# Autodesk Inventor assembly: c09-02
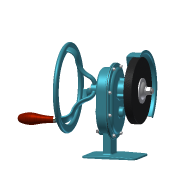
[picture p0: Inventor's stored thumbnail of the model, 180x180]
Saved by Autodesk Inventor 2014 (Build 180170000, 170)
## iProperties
Created: 2010-12
Part Number: c09-02
Document SubType Name: Assembly
Designer: Thom Tremblay
Author: Thom Tremblay
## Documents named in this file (27)
- C:\Inventor 2014 Essentials\Assemblies\Chapter 09\c09-02.iam
- C:\Inventor 2014 Essentials\Content Center Files\en-US\ANSI B93.98M\ANSI_B93.98M - 15x35x7-Type 2.ipt
- C:\Inventor 2014 Essentials\Content Center Files\en-US\SKF B - angular contact\SKF B7202 BE.ipt
- C:\Inventor 2014 Essentials\Content Center Files\en-US\IS 7483\IS 7483 - M4 x 8.ipt
- C:\Inventor 2014 Essentials\Content Center Files\en-US\ISO 2795  F\ISO 2795 - 10 x 14 x 10F.ipt
- C:\Inventor 2014 Essentials\Content Center Files\en-US\STN 022930\STN 022930 - 10.ipt
- C:\Inventor 2014 Essentials\Content Center Files\en-US\STN 022930\STN 022930 - 15.ipt
- C:\Inventor 2014 Essentials\Content Center Files\en-US\DIN 128\DIN 128 - A12.ipt
- C:\Inventor 2014 Essentials\Content Center Files\en-US\ISO 4032\ISO 4032 - M12ISO.ipt
- C:\Inventor 2014 Essentials\Content Center Files\en-US\ISO 4145 T8\ISO 4145 Plug T8 1_8.ipt
- C:\Inventor 2014 Essentials\Parts\Chapter 09\c09-01.ipt
- C:\Inventor 2014 Essentials\Parts\Chapter 09\c09-02.ipt
- C:\Inventor 2014 Essentials\Parts\Chapter 09\c09-03.ipt
- C:\Inventor 2014 Essentials\Parts\Chapter 09\c09-04.ipt
- C:\Inventor 2014 Essentials\Parts\Chapter 09\c09-05.ipt
- C:\Inventor 2014 Essentials\Parts\Chapter 09\c09-08.ipt
- C:\Inventor 2014 Essentials\Parts\Chapter 09\c09-06.ipt
- C:\Inventor 2014 Essentials\Parts\Chapter 09\c09-07.ipt
- C:\Inventor 2014 Essentials\Assemblies\Chapter 09\Design Accelerators\Shaft c09-01.iam
- C:\Inventor 2014 Essentials\Assemblies\Chapter 09\Design Accelerators\Shaft c09-02.iam
- C:\Inventor 2014 Essentials\Assemblies\Chapter 09\Design Accelerators\Shaft c09-03.iam
- C:\Inventor 2014 Essentials\Assemblies\Chapter 09\Design Accelerators\Cut Gear c09-01.iam
- C:\Inventor 2014 Essentials\Assemblies\Chapter 09\Design Accelerators\Cut Gear c09-02.iam
- C:\Inventor 2014 Essentials\Assemblies\Chapter 09\Design Accelerators\Spur Gear c09-01.iam
- C:\Inventor 2014 Essentials\Assemblies\Chapter 09\Design Accelerators\Key Connection c09-01.iam
- C:\Inventor 2014 Essentials\Assemblies\Chapter 09\Design Accelerators\Bolted Connection c09-01.iam
- C:\Inventor 2014 Essentials\Assemblies\Chapter 09\Design Accelerators\Bolted Connection c09-02.iam
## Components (31 placed, 24 different names)
1. c09-01:1 — Insert:1, Flush:3, Insert:27, Insert:28, Insert:39, Angle:19
2. c09-02:1 — Insert:1, Insert:17, Insert:18, Insert:25, Insert:26, Insert:40, Angle:19, Mate:18, Mate:19
3. ANSI/B93.98M 15x35x7-Type 2:1 — Insert:40
4. c09-03:1 — Flush:3
5. c09-04:1 — Insert:10, Angle:17, Insert:49, Mate:16, Angle:20
6. c09-05:1 — Insert:10
7. c09-08:1 — Insert:13, Insert:16, Insert:48
8. c09-08:2 — Insert:13
9. c09-06:1 — Insert:16, Angle:11
10. c09-07:1 — Insert:17, Insert:18
11. SKF B- Angular contact SKF B7202 BE:1 — Insert:25, Insert:45
12. IS 7483 M4 x 8:1
13. IS 7483 M4 x 8:2
14. ISO 2795 (Flanged) 10 x 14 x 10:1 — Insert:26
15. ISO 2795 (Flanged) 10 x 14 x 10:2 — Insert:27, Insert:46
16. ISO 2795 (Flanged) 10 x 14 x 10:3 — Insert:28, Insert:41
17. STN 022930 10:1 — Angle:16
18. STN 022930 15:1
19. STN 022930 15:2
20. DIN 128 A12:1 — Angle:10
21. ISO 4032 M12:1 — Angle:10, Angle:11, Angle:18
22. ISO 4145 Plug T8 1/8:1 — Insert:39
23. Input Shaft [sub-assembly] — Insert:41, Angle:16, Angle:17, Insert:49, Mate:17, Rotation:1, Rotation:2
24. Output Shaft:2 [sub-assembly] — Insert:45, Flush:4, Insert:48, Angle:18, Rotation:2
25. Transfer Shaft:1 [sub-assembly] — Insert:46, Mate:12, Flush:5, Angle:14, Mate:13, Angle:15, Rotation:1, Rotation:3
26. Cut Gear:1 [sub-assembly]
27. Cut Gear:2 [sub-assembly]
28. Cut Gear:3 [sub-assembly] — Mate:12, Flush:4, Angle:15, Rotation:3
29. Key Connection:1 [sub-assembly] — Flush:5, Angle:14, Mate:13
30. Housing Bolts:1 [sub-assembly] — Mate:18, Mate:19
31. Wheel Bolt [sub-assembly] — Mate:16, Mate:17, Angle:20
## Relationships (38: Insert 17, Angle 9, Mate 6, Flush 3, RelateRotation 3)
- Insert:1: c09-01:1 ↔ c09-02:1
- Flush:3: c09-01:1 ↔ c09-03:1
- Insert:10: c09-04:1 ↔ c09-05:1
- Insert:13: c09-08:1 ↔ c09-08:2
- Insert:16: c09-08:1 ↔ c09-06:1
- Insert:17: c09-02:1 ↔ c09-07:1
- Insert:18: c09-02:1 ↔ c09-07:1
- Insert:25: c09-02:1 ↔ SKF B- Angular contact SKF B7202 BE:1
- Insert:26: c09-02:1 ↔ ISO 2795 (Flanged) 10 x 14 x 10:1
- Insert:27: c09-01:1 ↔ ISO 2795 (Flanged) 10 x 14 x 10:2
- Insert:28: c09-01:1 ↔ ISO 2795 (Flanged) 10 x 14 x 10:3
- Angle:10: DIN 128 A12:1 ↔ ISO 4032 M12:1
- Angle:11: c09-06:1 ↔ ISO 4032 M12:1
- Insert:39: c09-01:1 ↔ ISO 4145 Plug T8 1/8:1
- Insert:40: c09-02:1 ↔ ANSI/B93.98M 15x35x7-Type 2:1
- Insert:41: ISO 2795 (Flanged) 10 x 14 x 10:3 ↔ Input Shaft
- Insert:45: SKF B- Angular contact SKF B7202 BE:1 ↔ Output Shaft:2
- Insert:46: ISO 2795 (Flanged) 10 x 14 x 10:2 ↔ Transfer Shaft:1
- Mate:12: Transfer Shaft:1 ↔ Cut Gear:3
- Flush:4: Output Shaft:2 ↔ Cut Gear:3
- Flush:5: Transfer Shaft:1 ↔ Key Connection:1
- Angle:14: Transfer Shaft:1 ↔ Key Connection:1
- Mate:13: Transfer Shaft:1 ↔ Key Connection:1
- Angle:15: Transfer Shaft:1 ↔ Cut Gear:3
- Angle:16: STN 022930 10:1 ↔ Input Shaft
- Angle:17: c09-04:1 ↔ Input Shaft
- Insert:48: c09-08:1 ↔ Output Shaft:2
- Angle:18: ISO 4032 M12:1 ↔ Output Shaft:2
- Insert:49: c09-04:1 ↔ Input Shaft
- Mate:16: c09-04:1 ↔ Wheel Bolt
- Mate:17: Input Shaft ↔ Wheel Bolt
- Angle:19: c09-01:1 ↔ c09-02:1
- Rotation:1 [RelateRotation]: Input Shaft ↔ Transfer Shaft:1
- Rotation:2 [RelateRotation]: Input Shaft ↔ Output Shaft:2
- Rotation:3 [RelateRotation]: Transfer Shaft:1 ↔ Cut Gear:3
- Mate:18: c09-02:1 ↔ Housing Bolts:1
- Mate:19: c09-02:1 ↔ Housing Bolts:1
- Angle:20: c09-04:1 ↔ Wheel Bolt
